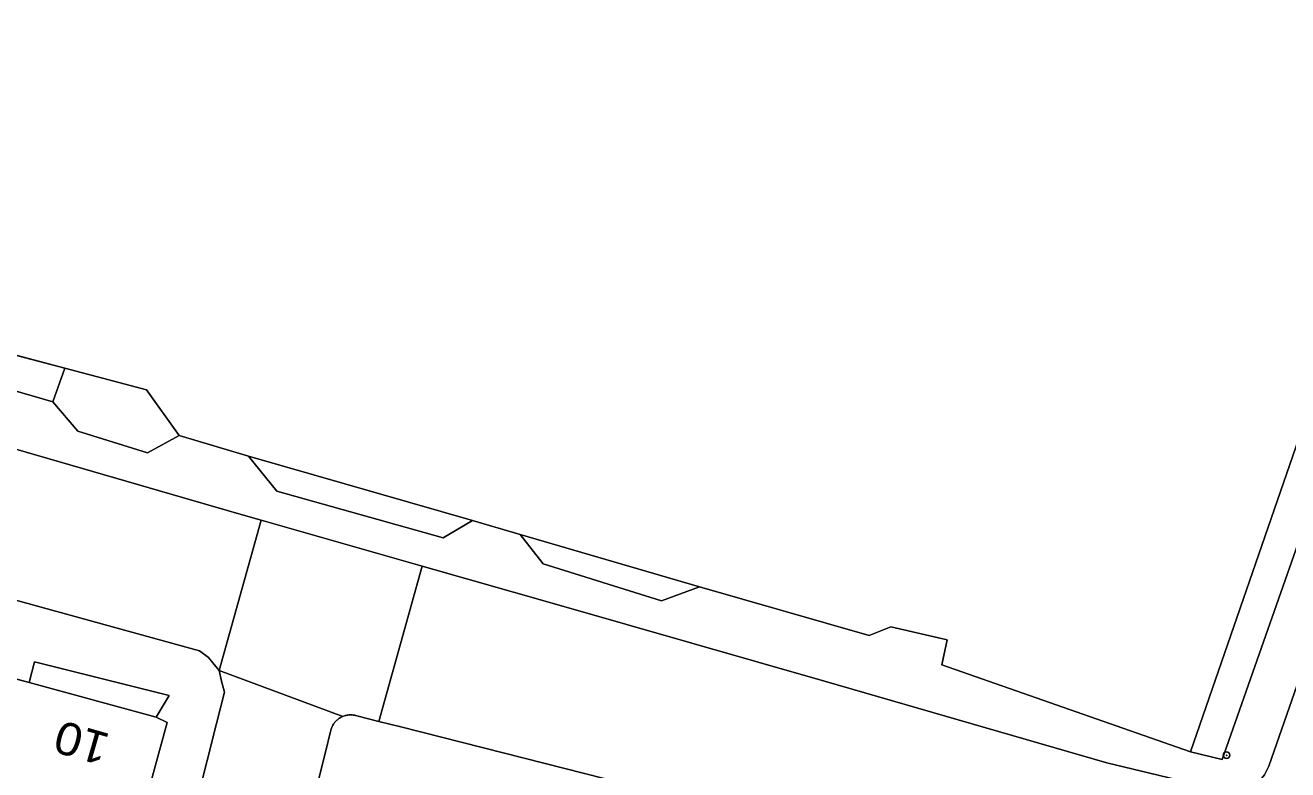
# Model space of a CAD drawing. Extents: x 528790 to 529292, y 179350 to 179856.
# Drawn here: x 529015 to 529073.1, y 179417.1 to 179451.4 of the extents above; entities that cross this region are included whole.
import ezdxf

# ---------------------------------------------------------------- set-up
doc = ezdxf.new("R2010")
doc.units = 0
doc.header["$LTSCALE"] = 0.6
doc.header["$PDMODE"] = 32
doc.header["$PDSIZE"] = 0.3
doc.layers.add('1', color=7, linetype='Continuous', lineweight=13)
doc.layers.add('2', color=7, linetype='Continuous', lineweight=13)
doc.layers.add('4', color=7, linetype='Continuous')
doc.layers.add('5', color=7, linetype='Continuous')

msp = doc.modelspace()

# ---------------------------------------------------------------- linework, layer by layer
at = {"layer": '1'}
for points in [[(529098.25, 179465.2), (529099.6, 179467.2), (529101.25, 179469.3), (529102.95, 179471.55), (529104.35, 179473.5), (529107.6, 179479.8), (529101.31, 179483.07), (529100.25, 179481.25), (529098.95, 179478.8), (529097.6, 179476.3), (529096.35, 179473.9), (529094.8, 179471.55), (529094, 179470.3), (529093, 179469.05), (529089.8, 179465.7), (529088.7, 179464.65), (529072.2, 179417.3), (529072, 179416.9), (529071.7, 179416.55), (529071.39, 179416.36), (529080.46, 179413.16)], [(529085.75, 179462.3), (529086.55, 179464.8), (529087.15, 179466.8), (529087.2, 179468), (529086.5, 179469.6), (529076.4, 179475.4), (529075.3, 179473.5), (529086.15, 179468.75), (529068.6, 179417.95), (529070.05, 179417.6)], [(529025.83, 179428.61), (529024.8, 179428.9), (529011.35, 179432.8), (529000, 179436.05), (528995, 179437.7), (528994.7, 179437.9), (528994.4, 179438.15), (528994.05, 179438.4), (528993.6, 179439.3), (528988.2, 179431.6), (528988.6, 179431.75), (528988.9, 179431.8), (528989.2, 179431.8), (528989.6, 179431.75), (528990, 179431.6), (529000, 179428.93), (529023, 179422.6), (529023.4, 179422.3), (529023.6, 179422.05), (529023.9, 179421.7)], [(529016.25, 179434.05), (529016.8, 179435.6), (529013.2, 179436.55), (529012.8, 179435.05)], [(529016.8, 179435.6), (529016.25, 179434.05), (529017.4, 179432.7), (529020.6, 179431.7), (529022.05, 179432.5), (529020.55, 179434.6)], [(529025.25, 179431.55), (529026.55, 179429.95), (529034.2, 179427.8), (529035.55, 179428.6)], [(529033.24, 179426.5), (529025.83, 179428.61), (529023.9, 179421.7), (529029.583, 179419.585), (529029.622, 179419.6), (529029.66, 179419.613), (529029.699, 179419.624), (529029.738, 179419.634), (529029.777, 179419.642), (529029.817, 179419.648), (529029.857, 179419.653), (529029.897, 179419.655), (529029.937, 179419.657), (529029.977, 179419.656), (529030.017, 179419.654), (529030.057, 179419.65), (529030.097, 179419.645), (529030.136, 179419.637), (529030.175, 179419.628), (529030.238, 179419.61), (529031.249, 179419.354)], [(529037.75, 179427.95), (529038.8, 179426.6), (529044.25, 179424.9), (529046, 179425.55)], [(529065.66, 179400.79), (529071.39, 179416.36), (529071.2, 179416.25), (529070.8, 179416), (529064.75, 179417.45), (529051.75, 179421.2), (529039.55, 179424.7), (529033.24, 179426.5), (529031.249, 179419.354), (529032.25, 179419.1), (529056.7, 179412.9), (529057, 179412.75), (529057.4, 179412.5), (529057.6, 179412.25), (529057.8, 179411.95), (529060.8, 179405.8), (529061.2, 179405), (529061.6, 179404.3), (529062.25, 179403.5)], [(529021, 179419.55), (529021.6, 179420.55), (529015.4, 179422.1), (529015.15, 179421.15)]]:
    msp.add_lwpolyline(points, close=True, dxfattribs=at)
for points in [[(529003.6, 179453.95), (529000, 179446.4), (528997.55, 179441.25), (528998.5, 179439.6), (529000, 179438.93), (529007.7, 179436.45), (529009.95, 179437.45), (529013.2, 179436.55), (529016.8, 179435.6), (529020.55, 179434.6), (529022.05, 179432.5), (529025.25, 179431.55), (529035.55, 179428.6), (529037.75, 179427.95), (529046, 179425.55), (529053.8, 179423.3), (529054.8, 179423.7), (529057.4, 179423.1), (529057.15, 179421.95), (529068.6, 179417.95), (529086.15, 179468.75)], [(529011.35, 179432.8), (529024.8, 179428.9), (529025.83, 179428.61), (529033.24, 179426.5), (529039.55, 179424.7), (529051.75, 179421.2), (529064.75, 179417.45), (529070.8, 179416), (529071.2, 179416.25), (529071.39, 179416.36), (529071.7, 179416.55), (529072, 179416.9), (529072.2, 179417.3), (529088.7, 179464.65)], [(529085.75, 179462.3), (529070.05, 179417.6), (529068.6, 179417.95), (529057.15, 179421.95), (529057.4, 179423.1), (529054.8, 179423.7), (529053.8, 179423.3), (529046, 179425.55), (529044.25, 179424.9), (529038.8, 179426.6), (529037.75, 179427.95), (529035.55, 179428.6), (529034.2, 179427.8), (529026.55, 179429.95), (529025.25, 179431.55), (529022.05, 179432.5), (529020.6, 179431.7), (529017.4, 179432.7), (529016.25, 179434.05), (529012.8, 179435.05)], [(529023.9, 179421.7), (529023.6, 179422.05), (529023.4, 179422.3), (529023, 179422.6), (529000, 179428.93)], [(529012.9, 179421.75), (529015.15, 179421.15), (529015.4, 179422.1), (529021.6, 179420.55), (529021, 179419.55), (529021.5, 179419.3), (529020.25, 179414.7), (529021.15, 179414.45), (529016.15, 179394.3), (529015.25, 179394.4), (529014.95, 179393.2)], [(529014.95, 179393.2), (529015.25, 179394.4), (529020.25, 179414.7), (529021.5, 179419.3), (529021, 179419.55), (529015.15, 179421.15), (529012.9, 179421.75)], [(529016.032, 179388.805), (529023.574, 179418.464), (529023.594, 179418.543), (529024.15, 179420.7), (529024, 179421.2), (529023.9, 179421.7)], [(529021.072, 179387.118), (529028.787, 179417.935), (529029.025, 179418.886), (529029.033, 179418.925), (529029.042, 179418.964), (529029.054, 179419.003), (529029.066, 179419.041), (529029.081, 179419.078), (529029.097, 179419.115), (529029.115, 179419.151), (529029.134, 179419.186), (529029.155, 179419.221), (529029.177, 179419.254), (529029.2, 179419.287), (529029.225, 179419.318), (529029.251, 179419.349), (529029.278, 179419.378), (529029.307, 179419.406), (529029.337, 179419.433), (529029.368, 179419.459), (529029.4, 179419.483), (529029.442, 179419.512), (529029.477, 179419.533), (529029.512, 179419.552), (529029.548, 179419.57), (529029.583, 179419.585), (529023.9, 179421.7), (529024, 179421.2), (529024.15, 179420.7), (529023.594, 179418.543), (529023.574, 179418.464), (529016.032, 179388.805)], [(529056.7, 179412.9), (529032.25, 179419.1), (529031.249, 179419.354), (529030.238, 179419.61), (529030.175, 179419.628), (529030.136, 179419.637), (529030.097, 179419.645), (529030.057, 179419.65), (529030.017, 179419.654), (529029.977, 179419.656), (529029.937, 179419.657), (529029.897, 179419.655), (529029.857, 179419.653), (529029.817, 179419.648), (529029.777, 179419.642), (529029.738, 179419.634), (529029.699, 179419.624), (529029.66, 179419.613), (529029.622, 179419.6), (529029.583, 179419.585), (529029.548, 179419.57), (529029.512, 179419.552), (529029.477, 179419.533), (529029.442, 179419.512), (529029.4, 179419.483), (529029.368, 179419.459), (529029.337, 179419.433), (529029.307, 179419.406), (529029.278, 179419.378), (529029.251, 179419.349), (529029.225, 179419.318), (529029.2, 179419.287), (529029.177, 179419.254), (529029.155, 179419.221), (529029.134, 179419.186), (529029.115, 179419.151), (529029.097, 179419.115), (529029.081, 179419.078), (529029.066, 179419.041), (529029.054, 179419.003), (529029.042, 179418.964), (529029.033, 179418.925), (529029.025, 179418.886), (529028.787, 179417.935), (529021.072, 179387.118)]]:
    msp.add_lwpolyline(points, dxfattribs=at)
at = {"layer": '2'}
for p, q in [((529013.2, 179436.55), (529016.8, 179435.6)), ((529016.25, 179434.05), (529016.8, 179435.6)), ((529016.25, 179434.05), (529012.8, 179435.05)), ((529022.05, 179432.5), (529025.25, 179431.55)), ((529025.25, 179431.55), (529035.55, 179428.6)), ((529023.9, 179421.7), (529025.83, 179428.61)), ((529033.24, 179426.5), (529025.83, 179428.61)), ((529035.55, 179428.6), (529037.75, 179427.95)), ((529037.75, 179427.95), (529046, 179425.55)), ((529031.249, 179419.354), (529033.24, 179426.5)), ((529015.15, 179421.15), (529012.9, 179421.75)), ((529023.9, 179421.7), (529029.583, 179419.585)), ((529015.15, 179421.15), (529021, 179419.55))]:
    msp.add_line(p, q, dxfattribs=at)
for points in [[(529071.39, 179416.36), (529071.7, 179416.55), (529072, 179416.9), (529072.2, 179417.3), (529088.7, 179464.65), (529089.8, 179465.7), (529093, 179469.05), (529094, 179470.3), (529094.8, 179471.55), (529096.35, 179473.9), (529097.6, 179476.3), (529098.95, 179478.8), (529100.25, 179481.25), (529101.31, 179483.07)], [(529068.6, 179417.95), (529086.15, 179468.75), (529075.3, 179473.5)], [(529087.2, 179468), (529087.15, 179466.8), (529086.55, 179464.8), (529085.75, 179462.3), (529070.05, 179417.6), (529068.6, 179417.95)], [(528993.6, 179439.3), (528994.05, 179438.4), (528994.4, 179438.15), (528994.7, 179437.9), (528995, 179437.7), (529000, 179436.05), (529011.35, 179432.8), (529024.8, 179428.9), (529025.83, 179428.61)], [(529016.8, 179435.6), (529020.55, 179434.6), (529022.05, 179432.5)], [(529022.05, 179432.5), (529020.6, 179431.7), (529017.4, 179432.7), (529016.25, 179434.05)], [(528988.2, 179431.6), (528988.6, 179431.75), (528988.9, 179431.8), (528989.2, 179431.8), (528989.6, 179431.75), (528990, 179431.6), (529000, 179428.93), (529023, 179422.6), (529023.4, 179422.3), (529023.6, 179422.05), (529023.9, 179421.7)], [(529035.55, 179428.6), (529034.2, 179427.8), (529026.55, 179429.95), (529025.25, 179431.55)], [(529046, 179425.55), (529044.25, 179424.9), (529038.8, 179426.6), (529037.75, 179427.95)], [(529071.39, 179416.36), (529071.2, 179416.25), (529070.8, 179416), (529064.75, 179417.45), (529051.75, 179421.2), (529039.55, 179424.7), (529033.24, 179426.5)], [(529046, 179425.55), (529053.8, 179423.3), (529054.8, 179423.7), (529057.4, 179423.1), (529057.15, 179421.95), (529068.6, 179417.95)], [(529021, 179419.55), (529021.6, 179420.55), (529015.4, 179422.1), (529015.15, 179421.15)], [(529023.9, 179421.7), (529024, 179421.2), (529024.15, 179420.7), (529023.594, 179418.543), (529023.574, 179418.464), (529016.032, 179388.805)], [(529020.25, 179414.7), (529021.5, 179419.3), (529021, 179419.55)], [(529021.072, 179387.118), (529028.787, 179417.935), (529029.025, 179418.886), (529029.033, 179418.925), (529029.042, 179418.964), (529029.054, 179419.003), (529029.066, 179419.041), (529029.081, 179419.078), (529029.097, 179419.115), (529029.115, 179419.151), (529029.134, 179419.186), (529029.155, 179419.221), (529029.177, 179419.254), (529029.2, 179419.287), (529029.225, 179419.318), (529029.251, 179419.349), (529029.278, 179419.378), (529029.307, 179419.406), (529029.337, 179419.433), (529029.368, 179419.459), (529029.4, 179419.483), (529029.442, 179419.512), (529029.477, 179419.533), (529029.512, 179419.552), (529029.548, 179419.57), (529029.583, 179419.585)], [(529029.583, 179419.585), (529029.622, 179419.6), (529029.66, 179419.613), (529029.699, 179419.624), (529029.738, 179419.634), (529029.777, 179419.642), (529029.817, 179419.648), (529029.857, 179419.653), (529029.897, 179419.655), (529029.937, 179419.657), (529029.977, 179419.656), (529030.017, 179419.654), (529030.057, 179419.65), (529030.097, 179419.645), (529030.136, 179419.637), (529030.175, 179419.628), (529030.238, 179419.61), (529031.249, 179419.354)], [(529065.66, 179400.79), (529062.25, 179403.5), (529061.6, 179404.3), (529061.2, 179405), (529060.8, 179405.8), (529057.8, 179411.95), (529057.6, 179412.25), (529057.4, 179412.5), (529057, 179412.75), (529056.7, 179412.9), (529032.25, 179419.1), (529031.249, 179419.354)]]:
    msp.add_lwpolyline(points, dxfattribs=at)
at = {"layer": '4'}
msp.add_point((529070.25, 179417.8), dxfattribs=at)

# ---------------------------------------------------------------- texts
at = {"layer": '5', "width": 1.1}
msp.add_text('10', height=1.5, rotation=164, dxfattribs=at).set_placement((529018.95, 179418.75))

doc.saveas('drawing.dxf')
